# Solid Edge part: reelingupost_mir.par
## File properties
Author: kaisa
Template: Iso Metric Part.par
Last saved by: kaisa
Revision: 6
Application: Solid Edge
Accuracy: 0.990
Username: kaisa
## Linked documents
ViluKaisa_reelingupost.par
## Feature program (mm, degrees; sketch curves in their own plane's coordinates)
part copy "CopiedPart_1"
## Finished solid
Body 1: solid body, 9 faces, 9 edges, 0 vertices.
  Faces by surface: cylinder 3, plane 3, torus 2, blend 1
  Edges by curve: circle 7, intersection 2
Bounding box of the edges (mm; curved faces can reach further): 3.000 x 4.000 x 17.000, from (-1.5, -2, 0) to (1.5, 2, 17).
Cylindrical faces by radius (mm): R1 x1, R1.5 x1, R2 x1
Toroidal faces (ring radius, tube radius in mm): R1.8 r0.3 x2
Planar faces by outward normal: +x 1, -x 1, -z 1
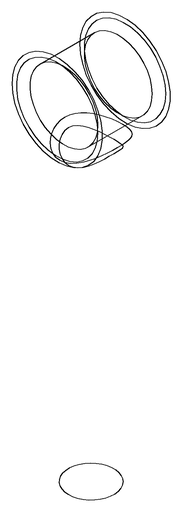
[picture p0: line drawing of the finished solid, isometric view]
